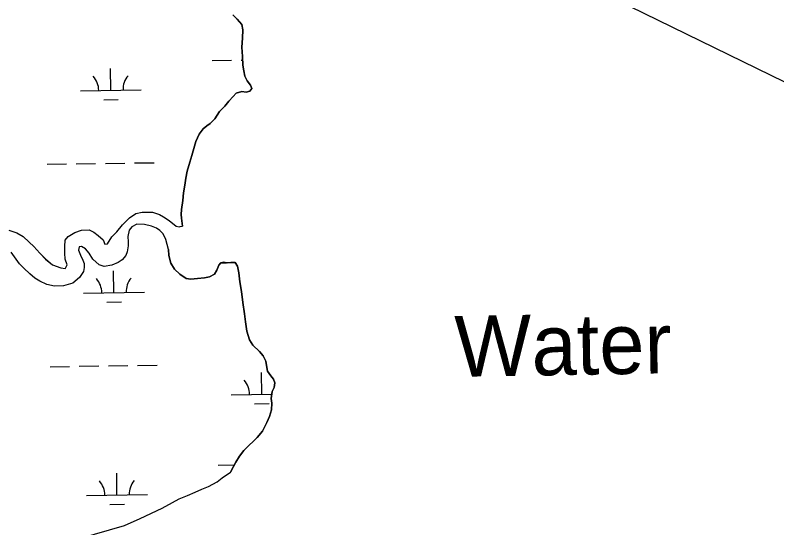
# Model space of a CAD drawing. Extents: x 3812694 to 3850888, y 319753 to 345638.
# Drawn here: x 3823804 to 3825056, y 337798 to 338641 of the extents above; entities that cross this region are included whole.
import ezdxf

# ---------------------------------------------------------------- set-up
doc = ezdxf.new("R2010")
doc.units = 0
for name, color, linetype in [('V-RIVR-IDEN', 7, 'Continuous'), ('V-TOPO-SHOR', 7, 'Continuous'), ('V-UTIL-LINE', 7, 'Continuous'), ('V-WETL-SWMP', 7, 'Continuous')]:
    doc.layers.add(name, color=color, linetype=linetype)

msp = doc.modelspace()

# ---------------------------------------------------------------- linework, layer by layer
at = {"layer": 'V-TOPO-SHOR'}
for points in [[(3824161.398, 338641.311), (3824168.8000000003, 338634.39900000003), (3824176.64, 338625.656), (3824178.085, 338616.663), (3824177.514, 338602.968), (3824176.629, 338588.51300000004), (3824177.258, 338572.829), (3824177.897, 338558.516), (3824179.644, 338549.216), (3824181.5530000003, 338540.827), (3824185.137, 338532.73), (3824190.56, 338525.988), (3824192.645, 338520.64), (3824189.714, 338516.10000000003), (3824183.611, 338514.478), (3824176.162, 338515.606), (3824167.307, 338512.485), (3824161.937, 338507.506), (3824155.17, 338499.34500000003), (3824148.557, 338491.485), (3824139.804, 338482.427), (3824132.245, 338470.618), (3824124.569, 338462.919), (3824118.755, 338459.163), (3824112.775, 338454.039), (3824106.461, 338445.417), (3824101.029, 338433.287), (3824097.429, 338421.597), (3824093.9820000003, 338410.05700000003), (3824090.693, 338399.124), (3824086.458, 338384.395), (3824084.535, 338372.996), (3824082.61, 338361.443), (3824080.6780000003, 338349.131), (3824079.2, 338336.357), (3824077.4, 338321.456), (3824076.724, 338313.547), (3824077.4280000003, 338306.995), (3824078.9930000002, 338294.043)], [(3823793.491, 338287.586), (3823806.3570000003, 338283.177), (3823816.865, 338277.221), (3823826.952, 338267.751), (3823834.3200000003, 338260.651), (3823844.392, 338249.616), (3823853.697, 338240.152), (3823864.9560000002, 338230.672), (3823878.989, 338225.47000000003), (3823886.02, 338224.629), (3823886.415, 338225.016), (3823889.199, 338230.467), (3823886.149, 338239.878), (3823885.451, 338249.659), (3823885.154, 338260.61), (3823885.633, 338271.163), (3823890.765, 338276.98600000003), (3823901.769, 338283.539), (3823912.751, 338287.357), (3823925.27, 338288.033), (3823933.061, 338284.447), (3823940.44, 338278.518), (3823948.199, 338271.413), (3823951.269, 338264.741), (3823955.574, 338265.09500000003), (3823962.71, 338276.373), (3823970.603, 338284.909), (3823980.085, 338296.56), (3823991.521, 338307.802), (3824002.1380000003, 338314.751), (3824012.714, 338317.00800000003), (3824022.102, 338317.319), (3824029.5300000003, 338317.255), (3824040.835, 338313.25), (3824047.843, 338309.67), (3824056.782, 338303.337), (3824068.433, 338293.853), (3824073.508, 338293.03), (3824075.075, 338293.407), (3824078.9930000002, 338294.043)], [(3824055.99, 338256.031), (3824051.433, 338272.101), (3824046.823, 338281.52400000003), (3824041.396, 338287.045), (3824036.341, 338290.609), (3824027.77, 338294.199), (3824016.453, 338297.034), (3824003.551, 338297.142), (3823995.3030000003, 338292.911), (3823991.347, 338287.471), (3823988.916, 338277.326), (3823989.62, 338268.325), (3823989.565, 338261.679), (3823987.916, 338251.916), (3823985.518, 338245.68200000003), (3823979.593, 338238.692), (3823972.911, 338234.449), (3823962.707, 338230.234), (3823949.7830000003, 338227.606), (3823941.986, 338230.41000000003), (3823931.508, 338239.882), (3823925.336, 338249.71), (3823919.1380000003, 338256.803), (3823912.917, 338260.765), (3823909.003, 338260.407), (3823907.784, 338254.943), (3823911.231, 338246.313), (3823914.682, 338238.463), (3823916.9820000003, 338232.968), (3823917.316, 338226.318), (3823916.0870000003, 338219.681), (3823909.744, 338209.568), (3823898.718, 338200.278), (3823883.04, 338196.108), (3823868.5670000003, 338195.451), (3823855.687, 338198.297), (3823844.392, 338203.477), (3823835.8340000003, 338208.632), (3823828.074, 338215.73600000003), (3823817.988, 338225.206), (3823810.619, 338232.306), (3823797.096, 338251.582)], [(3824055.99, 338256.031), (3824056.36, 338245.829), (3824059.6, 338233.169), (3824065.759, 338223.222), (3824074.5160000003, 338215.081), (3824085.112, 338207.989), (3824092.7120000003, 338206.858), (3824103.376, 338207.833), (3824114.9560000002, 338208.951), (3824123.344, 338211.011)], [(3824123.344, 338211.011), (3824131.295, 338215.054), (3824135.157, 338221.87200000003), (3824138.4220000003, 338229.759), (3824141.957, 338233.838), (3824146.685, 338235.016), (3824151.244, 338234.066), (3824158.095, 338234.311), (3824165.2490000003, 338234.25), (3824169.308, 338228.278), (3824171.35, 338217.608), (3824173.35, 338202.369), (3824175.806, 338186.669), (3824177.934, 338168.538), (3824180.518, 338150.249), (3824182.231, 338136.839), (3824184.537, 338121.598), (3824188.827, 338107.102), (3824194.541, 338098.681), (3824205.717, 338088.23600000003), (3824211.437, 338080.879), (3824216.0840000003, 338072.317), (3824217.518, 338061.8), (3824218.531, 338055.703), (3824223.944, 338047.89400000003), (3824228.464, 338042.529), (3824230.85, 338036.72500000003), (3824229.568, 338029.124), (3824226.316, 338022.303), (3824224.3910000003, 338010.903), (3824225.544, 338003.129), (3824224.9930000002, 337992.174), (3824222.011, 337981.545), (3824217.511, 337971.537), (3824210.386, 337956.98600000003), (3824201.623, 337946.70900000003), (3824195.481, 337940.52), (3824187.813, 337933.735), (3824179.6750000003, 337925.281), (3824172.7460000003, 337916.206), (3824166.268, 337906.214), (3824162.555, 337899.244), (3824157.759, 337890)], [(3823737.886, 337721.98600000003), (3823822.231, 337750.271), (3823881.1890000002, 337772.666), (3823983.552, 337801.868), (3824009.299, 337813.859), (3824045.162, 337830.804), (3824062.3370000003, 337840.123), (3824073.222, 337845.83), (3824087.16, 337851.512), (3824099.571, 337857.053), (3824110.602, 337861.846), (3824121.63, 337866.331), (3824136.042, 337873.68700000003), (3824144.1890000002, 337880.335), (3824157.759, 337890)]]:
    msp.add_lwpolyline(points, dxfattribs=at)
at = {"layer": 'V-UTIL-LINE'}
msp.add_lwpolyline([(3816680.7537181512, 342624.31255998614), (3826807.0130000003, 337683.41000000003), (3828506.861, 338360.794)], dxfattribs=at)
at = {"layer": 'V-WETL-SWMP'}
for p, q in [((3824127.412184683, 338566.44302218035), (3824159.4085237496, 338566.9270515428)), ((3824175.406693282, 338567.16906622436), (3824177.508686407, 338567.20086443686)), ((3823961.0695937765, 338517.49133766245), (3823960.5250608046, 338553.4872191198)), ((3823911.0753139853, 338516.7350417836), (3824011.0638735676, 338518.2476335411)), ((3823949.3043746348, 338501.88059201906), (3823973.3016289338, 338502.24361404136)), ((3823856.0540010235, 338395.8179607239), (3823888.0503400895, 338396.30199008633)), ((3823904.0485096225, 338396.5440047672), (3823936.0448486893, 338397.0280341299)), ((3823952.0430182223, 338397.2700488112), (3823984.0393572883, 338397.75407817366)), ((3824000.037526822, 338397.996092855), (3824032.0338658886, 338398.48012221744)), ((3824142.4302907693, 338233.9571476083), (3824151.130232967, 338234.0887572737)), ((3824152.4700793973, 338234.1090259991), (3824163.0362953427, 338234.26886799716)), ((3823966.101607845, 338184.8543970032), (3823965.5570748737, 338220.85027846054)), ((3823916.1073280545, 338184.0981011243), (3824016.095887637, 338185.6106928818)), ((3823954.336388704, 338169.2436513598), (3823978.3336430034, 338169.60667338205)), ((3823861.0860150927, 338063.18102006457), (3823893.0823541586, 338063.665049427)), ((3823909.080523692, 338063.9070641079), (3823941.0768627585, 338064.39109347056)), ((3823957.0750322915, 338064.6331081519), (3823989.071371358, 338065.11713751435)), ((3824005.0695408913, 338065.3591521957), (3824037.0658799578, 338065.8431815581)), ((3824209.1297999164, 338017.6982983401), (3824208.585266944, 338053.6941797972)), ((3824159.135520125, 338016.9420024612), (3824225.5799573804, 338017.9471505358)), ((3824197.364580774, 338002.0875526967), (3824221.361835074, 338002.45057471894)), ((3824137.476212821, 337901.16914086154), (3824163.7936259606, 337901.56726143)), ((3823971.133621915, 337852.21745634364), (3823970.5890889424, 337888.213337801)), ((3823921.139342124, 337851.4611604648), (3824021.1279017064, 337852.9737522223)), ((3823959.368402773, 337836.60671070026), (3823983.365657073, 337836.9697327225))]:
    msp.add_line(p, q, dxfattribs=at)
for points in [[(3824002.137, 338314.75), (3824012.713, 338317.007), (3824022.1010000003, 338317.318), (3824029.529, 338317.255), (3824040.835, 338313.249), (3824047.843, 338309.67), (3824056.7830000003, 338303.338), (3824068.433, 338293.854), (3824073.509, 338293.029), (3824075.076, 338293.407), (3824078.9930000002, 338294.043), (3824077.429, 338306.994), (3824076.723, 338313.54600000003), (3824077.399, 338321.455), (3824079.2, 338336.357), (3824080.679, 338349.131), (3824082.61, 338361.444), (3824084.535, 338372.996), (3824086.458, 338384.396), (3824090.693, 338399.125), (3824093.9820000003, 338410.05700000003), (3824097.429, 338421.596), (3824101.029, 338433.286), (3824106.46, 338445.417), (3824112.774, 338454.04), (3824118.754, 338459.164), (3824124.5700000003, 338462.92), (3824132.2460000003, 338470.618), (3824139.805, 338482.427), (3824148.558, 338491.48600000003), (3824155.171, 338499.34500000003), (3824161.937, 338507.507), (3824167.307, 338512.485), (3824176.162, 338515.606), (3824183.611, 338514.477), (3824189.714, 338516.10000000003), (3824192.644, 338520.641), (3824190.559, 338525.987), (3824185.136, 338532.73), (3824181.552, 338540.828), (3824179.644, 338549.216), (3824177.897, 338558.516), (3824177.257, 338572.83), (3824176.629, 338588.514), (3824177.5130000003, 338602.967), (3824178.086, 338616.662), (3824176.64, 338625.655), (3824168.799, 338634.398), (3824161.399, 338641.31)], [(3823793.492, 338287.587), (3823806.358, 338283.17600000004), (3823816.865, 338277.222), (3823826.951, 338267.751), (3823834.3200000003, 338260.65), (3823844.393, 338249.616), (3823853.697, 338240.153), (3823864.9560000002, 338230.673), (3823878.989, 338225.47000000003), (3823886.02, 338224.629), (3823886.415, 338225.016), (3823889.198, 338230.467), (3823886.15, 338239.877), (3823885.451, 338249.659), (3823885.153, 338260.61), (3823885.633, 338271.163), (3823890.7660000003, 338276.985), (3823901.77, 338283.539), (3823912.751, 338287.356), (3823925.27, 338288.032), (3823933.06, 338284.446), (3823940.4390000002, 338278.518), (3823948.199, 338271.414), (3823951.27, 338264.741), (3823955.575, 338265.09500000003), (3823962.7090000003, 338276.374), (3823970.602, 338284.91000000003), (3823980.085, 338296.56), (3823991.52, 338307.802), (3824002.137, 338314.75)], [(3824141.9560000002, 338233.839), (3824138.421, 338229.759), (3824135.157, 338221.87200000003), (3824131.294, 338215.055), (3824123.344, 338211.012), (3824114.955, 338208.952), (3824103.377, 338207.833), (3824092.713, 338206.858), (3824085.112, 338207.988), (3824074.517, 338215.08), (3824065.758, 338223.222), (3824059.6010000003, 338233.168), (3824056.36, 338245.83), (3824055.99, 338256.031), (3824051.434, 338272.102), (3824046.822, 338281.525), (3824041.395, 338287.04600000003), (3824036.342, 338290.608), (3824027.77, 338294.2), (3824016.454, 338297.033), (3824003.551, 338297.142), (3823995.304, 338292.911), (3823991.347, 338287.471), (3823988.915, 338277.325), (3823989.6210000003, 338268.325), (3823989.5640000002, 338261.678), (3823987.917, 338251.917), (3823985.518, 338245.681), (3823979.594, 338238.693), (3823972.91, 338234.44800000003), (3823962.708, 338230.234), (3823949.782, 338227.606), (3823941.985, 338230.41000000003), (3823931.508, 338239.88300000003), (3823925.335, 338249.711), (3823919.139, 338256.802), (3823912.917, 338260.765), (3823909.003, 338260.407), (3823907.784, 338254.943), (3823911.23, 338246.31200000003), (3823914.682, 338238.462), (3823916.9820000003, 338232.968), (3823917.316, 338226.318), (3823916.0870000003, 338219.681), (3823909.745, 338209.568), (3823898.717, 338200.277), (3823883.041, 338196.109), (3823868.568, 338195.45), (3823855.688, 338198.297), (3823844.392, 338203.476), (3823835.8340000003, 338208.632), (3823828.074, 338215.73600000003), (3823817.987, 338225.206), (3823810.6180000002, 338232.30700000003), (3823797.096, 338251.582)], [(3823881.188, 337772.666), (3823983.5530000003, 337801.868), (3824009.299, 337813.86), (3824045.161, 337830.804), (3824062.336, 337840.12200000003), (3824073.222, 337845.83), (3824087.161, 337851.512), (3824099.572, 337857.054), (3824110.602, 337861.84500000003), (3824121.631, 337866.331), (3824136.042, 337873.688), (3824144.188, 337880.335), (3824157.759, 337889.999), (3824162.556, 337899.244), (3824166.269, 337906.214), (3824172.747, 337916.206), (3824179.674, 337925.28), (3824187.813, 337933.735), (3824195.481, 337940.51900000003), (3824201.623, 337946.708), (3824210.386, 337956.985), (3824217.512, 337971.537), (3824222.011, 337981.545), (3824224.9930000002, 337992.175), (3824225.543, 338003.13), (3824224.3910000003, 338010.903), (3824226.315, 338022.302), (3824229.569, 338029.125), (3824230.8510000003, 338036.72500000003), (3824228.465, 338042.529), (3824223.944, 338047.895), (3824218.531, 338055.704), (3824217.517, 338061.80100000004), (3824216.0840000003, 338072.316), (3824211.438, 338080.88), (3824205.716, 338088.235), (3824194.541, 338098.681), (3824188.828, 338107.101), (3824184.537, 338121.598), (3824182.231, 338136.839), (3824180.518, 338150.249), (3824177.934, 338168.537), (3824175.805, 338186.669), (3824173.35, 338202.368), (3824171.349, 338217.607), (3824169.308, 338228.279), (3824165.2490000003, 338234.25), (3824158.095, 338234.311), (3824151.244, 338234.065), (3824146.685, 338235.017), (3824141.9560000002, 338233.839)]]:
    msp.add_lwpolyline(points, dxfattribs=at)
for centre, radius, start, end in [((3823905.8257958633, 338517.1304864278), 35.24628790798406, 0.0948642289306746, 41.63852256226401), ((3824016.2990280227, 338518.8016866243), 35.24628790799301, 140.09486122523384, 181.63851955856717), ((3823910.8578099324, 338184.4935457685), 35.24628790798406, 0.0948642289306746, 41.63852256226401), ((3824021.3310420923, 338186.164745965), 35.24628790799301, 140.09486122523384, 181.63851955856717), ((3824153.8860020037, 338017.3374471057), 35.24628790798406, 0.0948642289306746, 41.63852256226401), ((3823915.8898240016, 337851.856605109), 35.24628790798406, 0.0948642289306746, 41.63852256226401), ((3824026.363056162, 337853.5278053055), 35.24628790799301, 140.09486122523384, 181.63851955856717)]:
    msp.add_arc(centre, radius, start, end, dxfattribs=at)

# ---------------------------------------------------------------- texts
at = {"layer": 'V-RIVR-IDEN'}
msp.add_text('Water', height=99.99980199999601, rotation=0.9749999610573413, dxfattribs=at).set_placement((3824527.1219063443, 338046.405881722))

doc.saveas('drawing.dxf')
